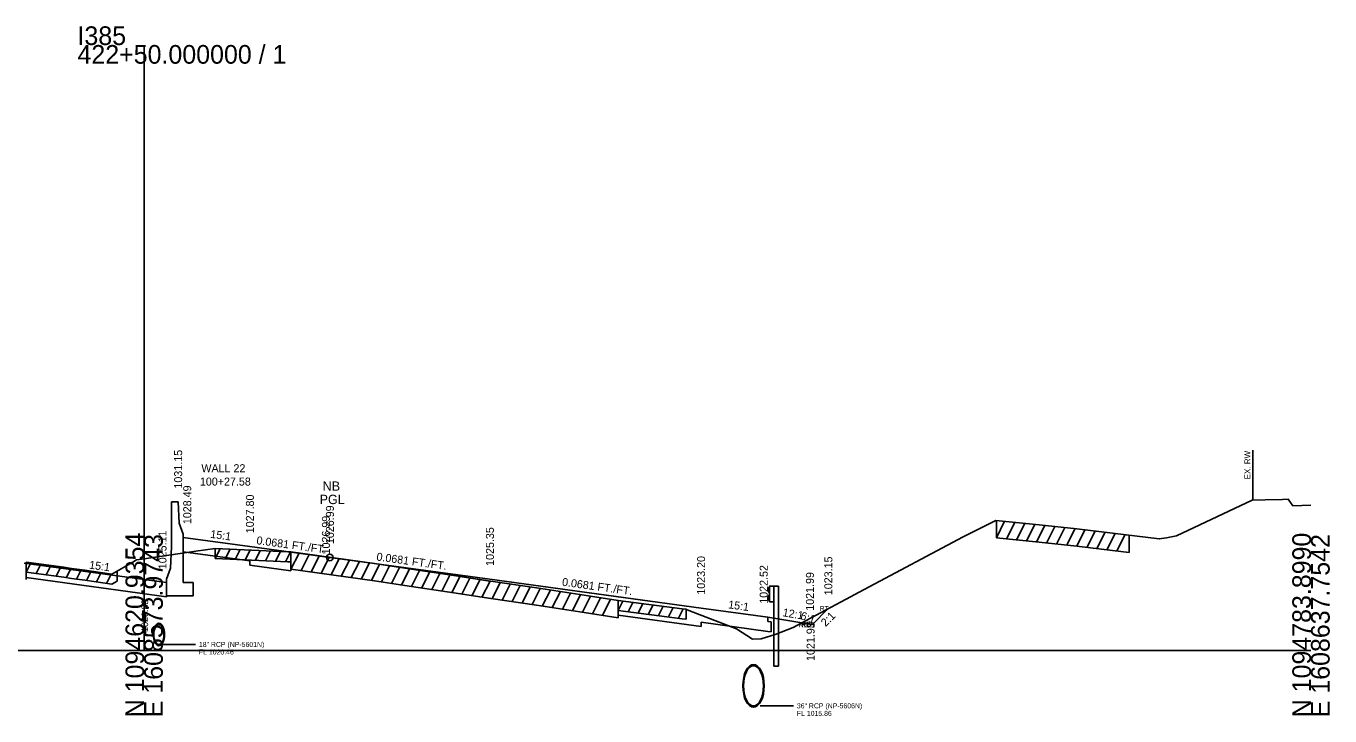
# Model space of a CAD drawing. Extents: x -26 to 1614813, y -18 to 1100051.
# Drawn here: x 4157.3 to 4352.8, y 8990.2 to 9093.7 of the extents above; entities that cross this region are included whole.
import ezdxf

# ---------------------------------------------------------------- set-up
doc = ezdxf.new("R2010")
doc.units = 0
for name, color, linetype in [('RD_EX_Misc', 7, 'Continuous'), ('RD_GPK_XS_Cell', 7, 'Continuous'), ('RD_HY_TX1', 7, 'Continuous'), ('RD_Sketch1', 7, 'Continuous'), ('RD_Sketch10', 7, 'Continuous'), ('RD_XS_Base', 7, 'Continuous'), ('RD_XS_CurbFront', 7, 'Continuous'), ('RD_XS_EarthShd', 7, 'Continuous'), ('RD_XS_ExGround', 7, 'Continuous'), ('RD_XS_ExPaveRet', 7, 'Continuous'), ('RD_XS_ExRW', 7, 'Continuous'), ('RD_XS_GR', 7, 'Continuous'), ('RD_XS_MedBbase', 7, 'Continuous'), ('RD_XS_MedBWall', 7, 'Continuous'), ('RD_XS_Pave', 7, 'Continuous'), ('RD_XS_PaveShd', 7, 'Continuous'), ('RD_XS_Pipe', 7, 'Continuous'), ('RD_XS_TieSlope', 7, 'Continuous'), ('RD_XS_TX_Elev_PR', 7, 'Continuous'), ('RD_XS_TX_Misc', 7, 'Continuous'), ('RD_XS_TX_ShdSlope', 7, 'Continuous'), ('RD_XS_TX_Slope', 7, 'Continuous')]:
    doc.layers.add(name, color=color, linetype=linetype)

msp = doc.modelspace()

# ---------------------------------------------------------------- linework, layer by layer
at = {"layer": 'RD_EX_Misc'}
for p, q in [((4185.65, 9013.83), (4185.65, 9015.33)), ((4157.29, 9011.76), (4157.29, 9013.26)), ((4185.65, 9013.83), (4196.55, 9013.33)), ((4196.55, 9013.33), (4197.02, 9013.31)), ((4197.02, 9014.81), (4197.02, 9013.31)), ((4197.02, 9013.31), (4197.02, 9013.31)), ((4157.29, 9011.76), (4162.93, 9011)), ((4162.93, 9011), (4164.1, 9010.84)), ((4170.95, 9011.93), (4170.95, 9010.43)), ((4164.1, 9010.84), (4166.09, 9010.55)), ((4166.09, 9010.55), (4170.16, 9009.98)), ((4170.16, 9009.98), (4170.95, 9010.43)), ((4246.08, 9006.03), (4246.08, 9007.53)), ((4246.08, 9006.03), (4255.7, 9004.78)), ((4256.27, 9006.21), (4256.27, 9004.71)), ((4255.7, 9004.78), (4256.26, 9004.72)), ((4256.26, 9004.72), (4256.27, 9004.71))]:
    msp.add_line(p, q, dxfattribs=at)
at = {"layer": 'RD_GPK_XS_Cell'}
for p, q in [((4175, 9000), (4175, 9090.85)), ((4000, 9000), (4175, 9000)), ((4175, 9000), (4350, 9000))]:
    msp.add_line(p, q, dxfattribs=at)
at = {"layer": 'RD_Sketch1'}
for p, q in [((4185.65, 9013.83), (4186.38, 9015.29)), ((4187.16, 9013.76), (4187.89, 9015.22)), ((4188.66, 9013.69), (4189.4, 9015.15)), ((4190.17, 9013.62), (4190.91, 9015.08)), ((4191.68, 9013.55), (4192.42, 9015.02)), ((4193.19, 9013.48), (4193.93, 9014.95)), ((4194.7, 9013.41), (4195.44, 9014.88)), ((4157.29, 9011.76), (4158, 9013.16)), ((4158.8, 9011.55), (4159.51, 9012.96)), ((4196.21, 9013.34), (4196.94, 9014.81)), ((4160.31, 9011.35), (4161.01, 9012.76)), ((4161.82, 9011.15), (4162.52, 9012.55)), ((4163.32, 9010.94), (4164.03, 9012.35)), ((4164.83, 9010.73), (4165.54, 9012.13)), ((4166.34, 9010.51), (4167.05, 9011.92)), ((4167.85, 9010.3), (4168.55, 9011.7)), ((4169.36, 9010.09), (4170.06, 9011.49)), ((4246.08, 9006.03), (4246.79, 9007.43)), ((4247.59, 9005.83), (4248.3, 9007.24)), ((4249.1, 9005.64), (4249.81, 9007.05)), ((4250.61, 9005.44), (4251.32, 9006.85)), ((4252.12, 9005.25), (4252.82, 9006.66)), ((4253.62, 9005.05), (4254.33, 9006.46)), ((4255.13, 9004.86), (4255.84, 9006.27))]:
    msp.add_line(p, q, dxfattribs=at)
at = {"layer": 'RD_Sketch10'}
for p, q in [((4190.86, 9015.61), (4202.86, 9013.98)), ((4202.86, 9013.98), (4226.86, 9010.71)), ((4226.86, 9010.71), (4250.86, 9007.44))]:
    msp.add_line(p, q, dxfattribs=at)
at = {"layer": 'RD_XS_Base'}
for p, q in [((4157.29, 9010.95), (4157.29, 9013.09)), ((4190.86, 9013.47), (4180.86, 9014.84)), ((4190.86, 9013.47), (4190.86, 9012.83)), ((4197.02, 9014.81), (4202.86, 9013.99)), ((4197.02, 9014.81), (4197.02, 9011.99)), ((4202.86, 9013.99), (4209.55, 9013.06)), ((4209.55, 9013.06), (4214.09, 9012.37)), ((4157.29, 9010.95), (4178.35, 9008.08)), ((4197.02, 9011.99), (4190.86, 9012.83)), ((4214.09, 9012.37), (4221.45, 9011.25)), ((4221.45, 9011.25), (4226.86, 9010.44)), ((4226.86, 9010.44), (4226.97, 9010.42)), ((4226.97, 9010.42), (4233.84, 9009.41)), ((4233.84, 9009.41), (4240.35, 9008.41)), ((4240.35, 9008.41), (4246.08, 9007.53)), ((4246.08, 9007.53), (4246.08, 9007.53)), ((4246.08, 9007.53), (4246.08, 9005.31)), ((4246.08, 9005.31), (4258.52, 9003.62)), ((4258.52, 9004.26), (4268.52, 9002.89)), ((4258.52, 9004.26), (4258.52, 9003.62)), ((4268.52, 9005.03), (4268.52, 9004.39)), ((4268.52, 9004.39), (4269.02, 9004.33)), ((4269.02, 9004.33), (4269.02, 9002.83)), ((4268.52, 9002.89), (4269.02, 9002.83))]:
    msp.add_line(p, q, dxfattribs=at)
at = {"layer": 'RD_XS_CurbFront'}
for p, q in [((4180.86, 9016.97), (4180.86, 9014.84)), ((4178.35, 9010.21), (4178.35, 9008.21))]:
    msp.add_line(p, q, dxfattribs=at)
at = {"layer": 'RD_XS_EarthShd'}
msp.add_line((4268.52, 9005.03), (4274.85, 9003.98), dxfattribs=at)
at = {"layer": 'RD_XS_ExGround'}
msp.add_lwpolyline([(4157.29, 9013.26), (4162.93, 9012.5), (4164.1, 9012.34), (4166.09, 9012.05), (4170.16, 9011.48), (4173.31, 9013.28), (4173.87, 9013.6), (4175, 9013.77), (4182.77, 9014.91), (4185.64, 9015.33), (4196.55, 9014.83), (4197.02, 9014.81), (4209.55, 9013.06), (4214.09, 9012.37), (4221.45, 9011.25), (4226.97, 9010.42), (4233.84, 9009.41), (4240.35, 9008.41), (4246.08, 9007.53), (4255.7, 9006.28), (4256.26, 9006.22), (4256.71, 9006.02), (4263.85, 9003.25), (4266.25, 9001.74), (4267.54, 9001.75), (4269.62, 9002.4), (4272.36, 9003.49), (4273.53, 9004.12), (4279.53, 9007.33), (4282.99, 9009.19), (4297.85, 9017.09), (4302.72, 9019.54), (4309.24, 9018.86), (4314.9, 9018.25), (4320.24, 9017.64), (4327.23, 9016.75), (4328.33, 9016.94), (4329.83, 9017.22), (4341.17, 9022.57), (4343.15, 9022.63), (4345.71, 9022.69), (4346.6, 9022.71), (4347.3, 9021.73), (4350, 9021.83)], dxfattribs=at)
at = {"layer": 'RD_XS_ExPaveRet'}
for p, q in [((4302.81, 9016.93), (4302.81, 9019.53)), ((4302.81, 9016.93), (4304.05, 9019.4)), ((4304.32, 9016.77), (4305.56, 9019.24)), ((4305.82, 9016.62), (4307.07, 9019.09)), ((4307.33, 9016.46), (4308.57, 9018.93)), ((4308.84, 9016.31), (4310.08, 9018.77)), ((4302.81, 9016.93), (4309.24, 9016.26)), ((4310.35, 9016.14), (4311.59, 9018.61)), ((4311.85, 9015.98), (4313.09, 9018.45)), ((4313.36, 9015.82), (4314.6, 9018.29)), ((4314.87, 9015.66), (4316.1, 9018.12)), ((4316.38, 9015.48), (4317.61, 9017.94)), ((4317.88, 9015.31), (4319.12, 9017.77)), ((4319.39, 9015.14), (4320.62, 9017.59)), ((4320.9, 9014.96), (4322.12, 9017.4)), ((4322.73, 9017.32), (4322.73, 9014.72)), ((4309.24, 9016.26), (4314.9, 9015.65)), ((4314.9, 9015.65), (4320.24, 9015.04)), ((4320.24, 9015.04), (4322.73, 9014.72)), ((4157.29, 9013.26), (4157.29, 9010.66)), ((4197.02, 9012.21), (4197.02, 9014.81)), ((4197.02, 9012.21), (4198.24, 9014.64)), ((4198.53, 9012), (4199.75, 9014.43)), ((4200.04, 9011.79), (4201.26, 9014.22)), ((4201.55, 9011.58), (4202.77, 9014.01)), ((4203.05, 9011.37), (4204.27, 9013.8)), ((4204.56, 9011.16), (4205.78, 9013.59)), ((4206.07, 9010.95), (4207.29, 9013.38)), ((4207.57, 9010.74), (4208.8, 9013.17)), ((4209.08, 9010.53), (4210.3, 9012.95)), ((4197.02, 9012.21), (4209.55, 9010.46)), ((4210.59, 9010.3), (4211.8, 9012.72)), ((4212.1, 9010.07), (4213.31, 9012.49)), ((4213.6, 9009.84), (4214.82, 9012.26)), ((4215.11, 9009.61), (4216.32, 9012.03)), ((4216.62, 9009.38), (4217.83, 9011.8)), ((4218.13, 9009.15), (4219.34, 9011.57)), ((4219.63, 9008.92), (4220.85, 9011.34)), ((4221.14, 9008.69), (4222.36, 9011.11)), ((4157.29, 9010.66), (4157.29, 9010.66)), ((4209.55, 9010.46), (4214.09, 9009.77)), ((4214.09, 9009.77), (4221.45, 9008.65)), ((4222.65, 9008.47), (4223.86, 9010.89)), ((4224.16, 9008.24), (4225.37, 9010.66)), ((4225.66, 9008.02), (4226.88, 9010.44)), ((4227.17, 9007.79), (4228.39, 9010.22)), ((4228.68, 9007.57), (4229.89, 9009.99)), ((4230.18, 9007.35), (4231.4, 9009.77)), ((4231.69, 9007.13), (4232.91, 9009.55)), ((4233.2, 9006.91), (4234.41, 9009.33)), ((4234.71, 9006.68), (4235.92, 9009.09)), ((4221.45, 9008.65), (4226.97, 9007.82)), ((4226.97, 9007.82), (4233.84, 9006.81)), ((4236.21, 9006.45), (4237.43, 9008.86)), ((4237.72, 9006.22), (4238.93, 9008.63)), ((4239.23, 9005.99), (4240.44, 9008.4)), ((4240.74, 9005.75), (4241.95, 9008.17)), ((4242.24, 9005.52), (4243.46, 9007.93)), ((4243.75, 9005.29), (4244.96, 9007.7)), ((4246.08, 9007.53), (4246.08, 9004.93)), ((4233.84, 9006.81), (4240.35, 9005.81)), ((4240.35, 9005.81), (4246.08, 9004.93)), ((4246.08, 9004.93), (4246.08, 9004.93))]:
    msp.add_line(p, q, dxfattribs=at)
at = {"layer": 'RD_XS_ExRW'}
msp.add_line((4341.28, 9030.09), (4341.28, 9022.57), dxfattribs=at)
at = {"layer": 'RD_XS_GR'}
for p, q in [((4268.55, 9009.27), (4268.7, 9009.49)), ((4268.55, 9009.02), (4268.76, 9008.71)), ((4268.79, 9009.53), (4268.71, 9009.5)), ((4268.55, 9008), (4268.76, 9008.31)), ((4268.55, 9007.75), (4268.7, 9007.53)), ((4268.79, 9007.49), (4268.71, 9007.52))]:
    msp.add_line(p, q, dxfattribs=at)
for points in [[(4269.46, 9009.68), (4268.79, 9009.68), (4268.79, 9007.34), (4269.46, 9007.34)], [(4270.13, 9009.68), (4269.46, 9009.68), (4269.46, 8997.68), (4270.13, 8997.68)]]:
    msp.add_lwpolyline(points, close=True, dxfattribs=at)
for centre, major_axis, start_param, end_param in [((4268.6, 9009.15), (0, -0.156), 3.787686, 5.637551), ((4268.72, 9009.44), (0, 0.0626), 0.174533, 0.6458), ((4268.6, 9007.87), (0, -0.156), 3.787227, 5.637092), ((4268.72, 9007.58), (0, -0.0626), 5.637385, 6.108652), ((4268.72, 9008.58), (0, 0.156), 4.712389, 5.637385), ((4268.72, 9008.44), (0, -0.156), 0.6458, 1.570796)]:
    msp.add_ellipse(centre, major_axis=major_axis, ratio=0.5, start_param=start_param, end_param=end_param, dxfattribs=at)
at = {"layer": 'RD_XS_MedBbase'}
for p, q in [((4180.86, 9010.21), (4180.86, 9014.84)), ((4182.36, 9010.21), (4180.86, 9010.21)), ((4182.36, 9008.21), (4182.36, 9010.21)), ((4178.35, 9008.21), (4182.36, 9008.21)), ((4178.35, 9008.08), (4178.35, 9008.21))]:
    msp.add_line(p, q, dxfattribs=at)
at = {"layer": 'RD_XS_MedBWall'}
for p, q in [((4179.11, 9022.31), (4179.11, 9015.55)), ((4180.1, 9022.31), (4179.11, 9022.31)), ((4180.27, 9019.14), (4180.1, 9022.31)), ((4180.86, 9017.47), (4180.27, 9019.14)), ((4180.86, 9016.97), (4180.86, 9017.47)), ((4178.94, 9012.38), (4179.11, 9015.55)), ((4178.35, 9010.71), (4178.94, 9012.38)), ((4178.35, 9010.21), (4178.35, 9010.71))]:
    msp.add_line(p, q, dxfattribs=at)
at = {"layer": 'RD_XS_Pave'}
for p, q in [((4202.86, 9013.98), (4190.86, 9015.61)), ((4202.86, 9013.98), (4226.86, 9010.71)), ((4226.86, 9010.71), (4258.52, 9006.39))]:
    msp.add_line(p, q, dxfattribs=at)
at = {"layer": 'RD_XS_PaveShd'}
for p, q in [((4190.86, 9015.61), (4180.86, 9016.97)), ((4157, 9013.13), (4178.35, 9010.21)), ((4258.52, 9006.39), (4268.52, 9005.03))]:
    msp.add_line(p, q, dxfattribs=at)
at = {"layer": 'RD_XS_Pipe'}
for p, q in [((4177.71, 9000.92), (4182.71, 9000.92)), ((4267.39, 8991.71), (4272.39, 8991.71))]:
    msp.add_line(p, q, dxfattribs=at)
for centre, major_axis in [((4177.21, 9002.42), (0, 1.7)), ((4177.21, 9002.42), (0, 1.5)), ((4266.39, 8994.71), (0, 3.2)), ((4266.39, 8994.71), (0, 3))]:
    msp.add_ellipse(centre, major_axis=major_axis, ratio=0.5, dxfattribs=at)
at = {"layer": 'RD_XS_TieSlope'}
for p, q in [((4275.17, 9003.87), (4277.61, 9006.31)), ((4274.85, 9003.98), (4275.17, 9003.87))]:
    msp.add_line(p, q, dxfattribs=at)
at = {"layer": 'RD_XS_TX_Misc'}
msp.add_circle((4202.86, 9013.98), 0.5, dxfattribs=at)

# ---------------------------------------------------------------- texts
at = {"layer": 'RD_GPK_XS_Cell'}
for s, p in [('I385', (4165, 9090.85)), ('422+50.000000 / 1', (4165, 9088.05))]:
    msp.add_text(s, height=2.8, dxfattribs=at).set_placement(p)
for s, p in [('N 1094620.9354', (4175, 8990)), ('E 1608573.9743', (4177.8, 8990)), ('N 1094783.8990', (4350, 8990)), ('E 1608637.7542', (4352.8, 8990))]:
    msp.add_text(s, height=2.8, rotation=90, dxfattribs=at).set_placement(p)
at = {"layer": 'RD_HY_TX1'}
for s, p in [('RT', (4276.31, 9005.93)), ('RD2', (4273.18, 9003.49)), ('RS', (4273.54, 9003.6)), ('RD1', (4273.56, 9003.49))]:
    msp.add_text(s, height=0.75, dxfattribs=at).set_placement(p)
at = {"layer": 'RD_Sketch10'}
msp.add_text(' 1026.99', height=1.2, rotation=90, dxfattribs=at).set_placement((4202.86, 9013.98))
at = {"layer": 'RD_XS_ExGround'}
msp.add_text('1026.88', height=1, rotation=90, dxfattribs=at).set_placement((4175.6, 9002.81))
at = {"layer": 'RD_XS_ExRW'}
msp.add_text('EX. RW', height=0.9, rotation=90, dxfattribs=at).set_placement((4340.92, 9025.69))
at = {"layer": 'RD_XS_Pipe'}
for s, p in [('18" RCP (NP-5601N)', (4183.21, 9000.55)), ('FL 1020.46', (4183.21, 8999.42)), ('36" RCP (NP-5606N)', (4272.89, 8991.34)), ('FL 1015.86', (4272.89, 8990.21))]:
    msp.add_text(s, height=0.75, dxfattribs=at).set_placement(p)
at = {"layer": 'RD_XS_TX_Elev_PR'}
for s, p in [('1031.15', (4180.7, 9024.31)), ('1028.49', (4182.06, 9018.97)), ('1027.80', (4191.46, 9017.61)), ('1026.99', (4203.46, 9015.98)), ('1025.11', (4178.35, 9012.21)), ('1025.35', (4227.46, 9012.71)), ('1023.20', (4259.12, 9008.39)), ('1023.15', (4278.21, 9008.31)), ('1022.52', (4268.52, 9007.03)), ('1021.99', (4275.45, 9005.98)), ('1021.93', (4275.55, 8998.45))]:
    msp.add_text(s, height=1.2, rotation=90, dxfattribs=at).set_placement(p)
at = {"layer": 'RD_XS_TX_Misc'}
for s, height, p in [('WALL 22', 1.2, (4183.58, 9026.76)), ('100+27.58', 1.2, (4183.36, 9024.76)), ('NB', 1.4, (4201.78, 9023.98)), ('PGL', 1.4, (4201.32, 9021.98))]:
    msp.add_text(s, height=height, dxfattribs=at).set_placement(p)
at = {"layer": 'RD_XS_TX_ShdSlope'}
for s, rotation, p in [('15:1', 352.2426, (4184.87, 9016.93)), ('15:1', 352.2215, (4166.7, 9012.31)), ('15:1', 352.2436, (4262.54, 9006.35)), ('12:1', 350.5377, (4270.69, 9005.17))]:
    msp.add_text(s, height=1.2, rotation=rotation, dxfattribs=at).set_placement(p)
at = {"layer": 'RD_XS_TX_Slope'}
for s, rotation, p in [('0.0681 FT./FT.', 352.2426, (4191.79, 9015.98)), ('0.0681 FT./FT.', 352.2431, (4209.79, 9013.53)), ('0.0681 FT./FT.', 352.2436, (4237.62, 9009.74)), ('6:1', 341.6089, (4273.32, 9004.75)), ('2:1', 44.9269, (4277.2, 9003.53))]:
    msp.add_text(s, height=1.2, rotation=rotation, dxfattribs=at).set_placement(p)

doc.saveas('drawing.dxf')
